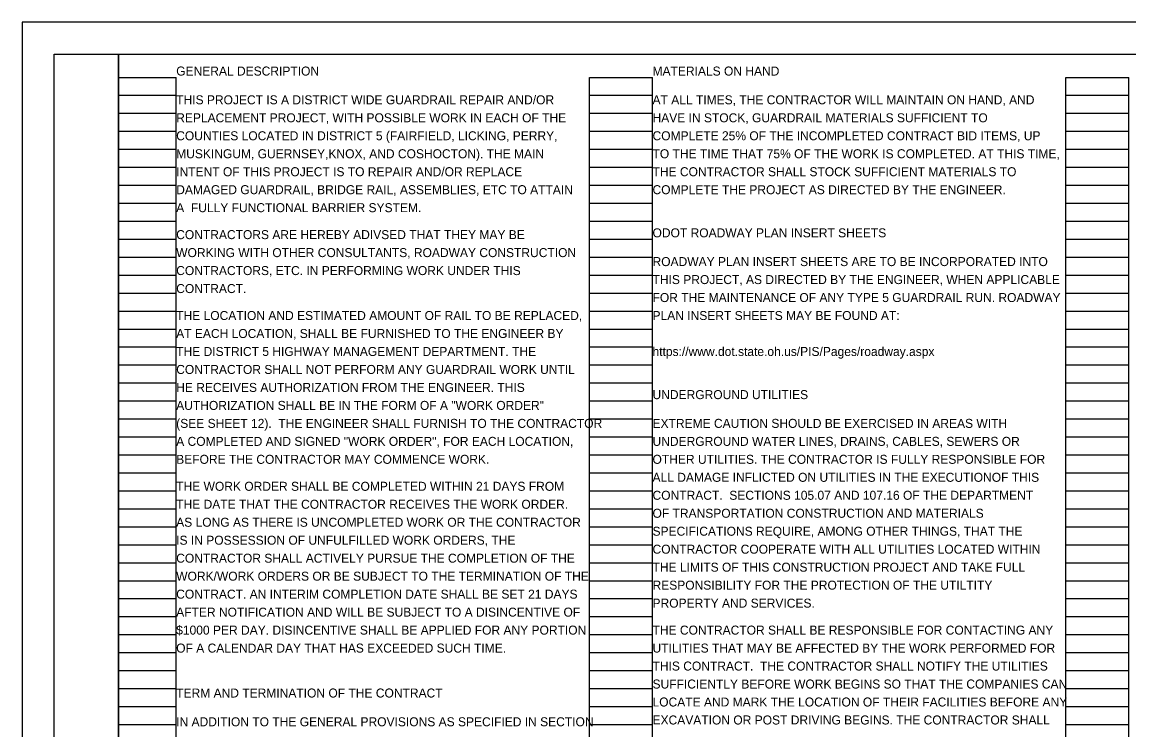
# Model space of a CAD drawing. Extents: x 0 to 34, y 0 to 22.
# Drawn here: x 0 to 17.24, y 10.98 to 22 of the extents above; entities that cross this region are included whole.
import ezdxf

# ---------------------------------------------------------------- set-up
doc = ezdxf.new("R2010")
doc.units = 0
for name, color, linetype in [('SH_Border', 7, 'Continuous'), ('SH_Cut_Line', 7, 'Continuous'), ('SH_Data', 7, 'Continuous'), ('SH_Text', 7, 'Continuous')]:
    doc.layers.add(name, color=color, linetype=linetype)

msp = doc.modelspace()

# ---------------------------------------------------------------- linework, layer by layer
at = {"layer": 'SH_Border'}
for points in [[(0.5, 21.5), (1.5, 21.5), (1.5, 0.5), (0.5, 0.5)], [(1.5, 21.5), (33.5, 21.5), (33.5, 0.5), (1.5, 0.5)]]:
    msp.add_lwpolyline(points, close=True, dxfattribs=at)
at = {"layer": 'SH_Cut_Line'}
msp.add_lwpolyline([(0, 0), (34, 0), (34, 22), (0, 22)], close=True, dxfattribs=at)
at = {"layer": 'SH_Data'}
for p, q in [((1.5, 0.98), (1.5, 21.14)), ((1.5, 21.14), (2.4, 21.14)), ((2.4, 0.98), (2.4, 21.14)), ((8.84, 0.98), (8.84, 21.14)), ((8.84, 21.14), (9.82, 21.14)), ((9.82, 0.98), (9.82, 21.14)), ((16.26, 0.98), (16.26, 21.14)), ((16.26, 21.14), (17.24, 21.14)), ((17.24, 0.98), (17.24, 21.14)), ((1.5, 20.86), (2.4, 20.86)), ((8.84, 20.86), (9.82, 20.86)), ((16.26, 20.86), (17.24, 20.86)), ((1.5, 20.58), (2.4, 20.58)), ((8.84, 20.58), (9.82, 20.58)), ((16.26, 20.58), (17.24, 20.58)), ((1.5, 20.3), (2.4, 20.3)), ((8.84, 20.3), (9.82, 20.3)), ((16.26, 20.3), (17.24, 20.3)), ((1.5, 20.02), (2.4, 20.02)), ((8.84, 20.02), (9.82, 20.02)), ((16.26, 20.02), (17.24, 20.02)), ((1.5, 19.74), (2.4, 19.74)), ((8.84, 19.74), (9.82, 19.74)), ((16.26, 19.74), (17.24, 19.74)), ((1.5, 19.46), (2.4, 19.46)), ((8.84, 19.46), (9.82, 19.46)), ((16.26, 19.46), (17.24, 19.46)), ((1.5, 19.18), (2.4, 19.18)), ((8.84, 19.18), (9.82, 19.18)), ((16.26, 19.18), (17.24, 19.18)), ((1.5, 18.9), (2.4, 18.9)), ((8.84, 18.9), (9.82, 18.9)), ((16.26, 18.9), (17.24, 18.9)), ((1.5, 18.62), (2.4, 18.62)), ((8.84, 18.62), (9.82, 18.62)), ((16.26, 18.62), (17.24, 18.62)), ((1.5, 18.34), (2.4, 18.34)), ((8.84, 18.34), (9.82, 18.34)), ((16.26, 18.34), (17.24, 18.34)), ((1.5, 18.06), (2.4, 18.06)), ((8.84, 18.06), (9.82, 18.06)), ((16.26, 18.06), (17.24, 18.06)), ((1.5, 17.78), (2.4, 17.78)), ((8.84, 17.78), (9.82, 17.78)), ((16.26, 17.78), (17.24, 17.78)), ((1.5, 17.5), (2.4, 17.5)), ((8.84, 17.5), (9.82, 17.5)), ((16.26, 17.5), (17.24, 17.5)), ((1.5, 17.22), (2.4, 17.22)), ((8.84, 17.22), (9.82, 17.22)), ((16.26, 17.22), (17.24, 17.22)), ((1.5, 16.94), (2.4, 16.94)), ((8.84, 16.94), (9.82, 16.94)), ((16.26, 16.94), (17.24, 16.94)), ((1.5, 16.66), (2.4, 16.66)), ((8.84, 16.66), (9.82, 16.66)), ((16.26, 16.66), (17.24, 16.66)), ((1.5, 16.38), (2.4, 16.38)), ((8.84, 16.38), (9.82, 16.38)), ((16.26, 16.38), (17.24, 16.38)), ((1.5, 16.1), (2.4, 16.1)), ((8.84, 16.1), (9.82, 16.1)), ((16.26, 16.1), (17.24, 16.1)), ((1.5, 15.82), (2.4, 15.82)), ((8.84, 15.82), (9.82, 15.82)), ((16.26, 15.82), (17.24, 15.82)), ((1.5, 15.54), (2.4, 15.54)), ((8.84, 15.54), (9.82, 15.54)), ((16.26, 15.54), (17.24, 15.54)), ((1.5, 15.26), (2.4, 15.26)), ((8.84, 15.26), (9.82, 15.26)), ((16.26, 15.26), (17.24, 15.26)), ((1.5, 14.98), (2.4, 14.98)), ((8.84, 14.98), (9.82, 14.98)), ((16.26, 14.98), (17.24, 14.98)), ((1.5, 14.7), (2.4, 14.7)), ((8.84, 14.7), (9.82, 14.7)), ((16.26, 14.7), (17.24, 14.7)), ((1.5, 14.42), (2.4, 14.42)), ((8.84, 14.42), (9.82, 14.42)), ((16.26, 14.42), (17.24, 14.42)), ((1.5, 14.14), (2.4, 14.14)), ((8.84, 14.14), (9.82, 14.14)), ((16.26, 14.14), (17.24, 14.14)), ((1.5, 13.86), (2.4, 13.86)), ((8.84, 13.86), (9.82, 13.86)), ((16.26, 13.86), (17.24, 13.86)), ((1.5, 13.58), (2.4, 13.58)), ((8.84, 13.58), (9.82, 13.58)), ((16.26, 13.58), (17.24, 13.58)), ((1.5, 13.3), (2.4, 13.3)), ((8.84, 13.3), (9.82, 13.3)), ((16.26, 13.3), (17.24, 13.3)), ((1.5, 13.02), (2.4, 13.02)), ((8.84, 13.02), (9.82, 13.02)), ((16.26, 13.02), (17.24, 13.02)), ((1.5, 12.74), (2.4, 12.74)), ((8.84, 12.74), (9.82, 12.74)), ((16.26, 12.74), (17.24, 12.74)), ((1.5, 12.46), (2.4, 12.46)), ((8.84, 12.46), (9.82, 12.46)), ((16.26, 12.46), (17.24, 12.46)), ((1.5, 12.18), (2.4, 12.18)), ((8.84, 12.18), (9.82, 12.18)), ((16.26, 12.18), (17.24, 12.18)), ((1.5, 11.9), (2.4, 11.9)), ((8.84, 11.9), (9.82, 11.9)), ((16.26, 11.9), (17.24, 11.9)), ((1.5, 11.62), (2.4, 11.62)), ((8.84, 11.62), (9.82, 11.62)), ((16.26, 11.62), (17.24, 11.62)), ((1.5, 11.34), (2.4, 11.34)), ((8.84, 11.34), (9.82, 11.34)), ((16.26, 11.34), (17.24, 11.34)), ((1.5, 11.06), (2.4, 11.06)), ((8.84, 11.06), (9.82, 11.06)), ((16.26, 11.06), (17.24, 11.06))]:
    msp.add_line(p, q, dxfattribs=at)

# ---------------------------------------------------------------- texts
at = {"layer": 'SH_Text'}
for s, p in [('GENERAL DESCRIPTION', (2.4, 21.168)), ('MATERIALS ON HAND', (9.82, 21.168)), ('THIS PROJECT IS A DISTRICT WIDE GUARDRAIL REPAIR AND/OR', (2.4, 20.72)), ('AT ALL TIMES, THE CONTRACTOR WILL MAINTAIN ON HAND, AND', (9.82, 20.72)), ('REPLACEMENT PROJECT, WITH POSSIBLE WORK IN EACH OF THE', (2.4, 20.44)), ('HAVE IN STOCK, GUARDRAIL MATERIALS SUFFICIENT TO', (9.82, 20.44)), ('COUNTIES LOCATED IN DISTRICT 5 (FAIRFIELD, LICKING, PERRY,', (2.4, 20.16)), ('COMPLETE 25% OF THE INCOMPLETED CONTRACT BID ITEMS, UP', (9.82, 20.16)), ('MUSKINGUM, GUERNSEY,KNOX, AND COSHOCTON). THE MAIN', (2.4, 19.88)), ('TO THE TIME THAT 75% OF THE WORK IS COMPLETED. AT THIS TIME,', (9.82, 19.88)), ('INTENT OF THIS PROJECT IS TO REPAIR AND/OR REPLACE', (2.4, 19.6)), ('THE CONTRACTOR SHALL STOCK SUFFICIENT MATERIALS TO', (9.82, 19.6)), ('DAMAGED GUARDRAIL, BRIDGE RAIL, ASSEMBLIES, ETC TO ATTAIN', (2.4, 19.32)), ('COMPLETE THE PROJECT AS DIRECTED BY THE ENGINEER.', (9.82, 19.32)), ('A  FULLY FUNCTIONAL BARRIER SYSTEM.', (2.4, 19.04)), ('CONTRACTORS ARE HEREBY ADIVSED THAT THEY MAY BE', (2.4, 18.62)), ('ODOT ROADWAY PLAN INSERT SHEETS', (9.82, 18.648)), ('WORKING WITH OTHER CONSULTANTS, ROADWAY CONSTRUCTION', (2.4, 18.34)), ('ROADWAY PLAN INSERT SHEETS ARE TO BE INCORPORATED INTO', (9.82, 18.2)), ('CONTRACTORS, ETC. IN PERFORMING WORK UNDER THIS', (2.4, 18.06)), ('THIS PROJECT, AS DIRECTED BY THE ENGINEER, WHEN APPLICABLE', (9.82, 17.92)), ('CONTRACT.', (2.4, 17.78)), ('FOR THE MAINTENANCE OF ANY TYPE 5 GUARDRAIL RUN. ROADWAY', (9.82, 17.64)), ('THE LOCATION AND ESTIMATED AMOUNT OF RAIL TO BE REPLACED,', (2.4, 17.36)), ('PLAN INSERT SHEETS MAY BE FOUND AT:  ', (9.82, 17.36)), ('AT EACH LOCATION, SHALL BE FURNISHED TO THE ENGINEER BY', (2.4, 17.08)), ('THE DISTRICT 5 HIGHWAY MANAGEMENT DEPARTMENT. THE', (2.4, 16.8)), ('https://www.dot.state.oh.us/PIS/Pages/roadway.aspx', (9.82, 16.8)), ('CONTRACTOR SHALL NOT PERFORM ANY GUARDRAIL WORK UNTIL', (2.4, 16.52)), ('HE RECEIVES AUTHORIZATION FROM THE ENGINEER. THIS', (2.4, 16.24)), ('UNDERGROUND UTILITIES', (9.82, 16.128)), ('AUTHORIZATION SHALL BE IN THE FORM OF A "WORK ORDER"', (2.4, 15.96)), ('(SEE SHEET 12).  THE ENGINEER SHALL FURNISH TO THE CONTRACTOR', (2.4, 15.68)), ('EXTREME CAUTION SHOULD BE EXERCISED IN AREAS WITH', (9.82, 15.68)), ('A COMPLETED AND SIGNED "WORK ORDER", FOR EACH LOCATION,', (2.4, 15.4)), ('UNDERGROUND WATER LINES, DRAINS, CABLES, SEWERS OR', (9.82, 15.4)), ('BEFORE THE CONTRACTOR MAY COMMENCE WORK.', (2.4, 15.12)), ('OTHER UTILITIES. THE CONTRACTOR IS FULLY RESPONSIBLE FOR ', (9.82, 15.12)), ('THE WORK ORDER SHALL BE COMPLETED WITHIN 21 DAYS FROM', (2.4, 14.7)), ('ALL DAMAGE INFLICTED ON UTILITIES IN THE EXECUTIONOF THIS', (9.82, 14.84)), ('CONTRACT.  SECTIONS 105.07 AND 107.16 OF THE DEPARTMENT', (9.82, 14.56)), ('THE DATE THAT THE CONTRACTOR RECEIVES THE WORK ORDER.', (2.4, 14.42)), ('OF TRANSPORTATION CONSTRUCTION AND MATERIALS', (9.82, 14.28)), ('AS LONG AS THERE IS UNCOMPLETED WORK OR THE CONTRACTOR', (2.4, 14.14)), ('SPECIFICATIONS REQUIRE, AMONG OTHER THINGS, THAT THE', (9.82, 14)), ('IS IN POSSESSION OF UNFULFILLED WORK ORDERS, THE', (2.4, 13.86)), ('CONTRACTOR COOPERATE WITH ALL UTILITIES LOCATED WITHIN', (9.82, 13.72)), ('CONTRACTOR SHALL ACTIVELY PURSUE THE COMPLETION OF THE', (2.4, 13.58)), ('WORK/WORK ORDERS OR BE SUBJECT TO THE TERMINATION OF THE', (2.4, 13.3)), ('THE LIMITS OF THIS CONSTRUCTION PROJECT AND TAKE FULL', (9.82, 13.44)), ('RESPONSIBILITY FOR THE PROTECTION OF THE UTILTITY', (9.82, 13.16)), ('CONTRACT. AN INTERIM COMPLETION DATE SHALL BE SET 21 DAYS', (2.4, 13.02)), ('PROPERTY AND SERVICES.', (9.82, 12.88)), ('AFTER NOTIFICATION AND WILL BE SUBJECT TO A DISINCENTIVE OF', (2.4, 12.74)), ('$1000 PER DAY. DISINCENTIVE SHALL BE APPLIED FOR ANY PORTION', (2.4, 12.46)), ('THE CONTRACTOR SHALL BE RESPONSIBLE FOR CONTACTING ANY', (9.82, 12.46)), ('OF A CALENDAR DAY THAT HAS EXCEEDED SUCH TIME.', (2.4, 12.18)), ('UTILITIES THAT MAY BE AFFECTED BY THE WORK PERFORMED FOR', (9.82, 12.18)), ('THIS CONTRACT.  THE CONTRACTOR SHALL NOTIFY THE UTILITIES', (9.82, 11.9)), ('SUFFICIENTLY BEFORE WORK BEGINS SO THAT THE COMPANIES CAN', (9.82, 11.62)), ('TERM AND TERMINATION OF THE CONTRACT', (2.4, 11.48)), ('LOCATE AND MARK THE LOCATION OF THEIR FACILITIES BEFORE ANY', (9.82, 11.34)), ('IN ADDITION TO THE GENERAL PROVISIONS AS SPECIFIED IN SECTION', (2.4, 11.032)), ('EXCAVATION OR POST DRIVING BEGINS. THE CONTRACTOR SHALL', (9.82, 11.06))]:
    msp.add_text(s, height=0.14, dxfattribs=at).set_placement(p)

doc.saveas('drawing.dxf')
